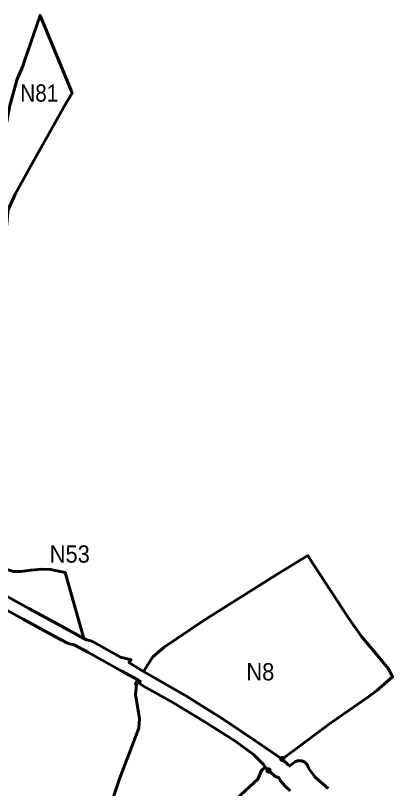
# Model space of a CAD drawing. Extents: x -650277 to -643422, y -1073980 to -1066720.
# Drawn here: x -645952 to -645426, y -1069207 to -1068130 of the extents above; entities that cross this region are included whole.
import ezdxf

# ---------------------------------------------------------------- set-up
doc = ezdxf.new("R2010")
doc.units = 0
doc.header["$LTSCALE"] = 9.6
doc.header["$PDMODE"] = 32
doc.header["$PDSIZE"] = 4.8
for name, color, linetype, lineweight in [('42', 7, 'Continuous', 60), ('48', 7, 'Continuous', 60), ('60', 7, 'Continuous', 60), ('63', 7, 'Continuous', 25), ('7', 7, 'Continuous', 60)]:
    doc.layers.add(name, color=color, linetype=linetype, lineweight=lineweight)

msp = doc.modelspace()

# ---------------------------------------------------------------- linework, layer by layer
at = {"layer": '42'}
for points in [[(-645973.36, -1068898.93), (-645954.59, -1068904.41), (-645944.23, -1068904.13), (-645930.1, -1068902.47), (-645915.61, -1068901.02), (-645902.91, -1068901.43), (-645882.63, -1068905.88), (-645856.26, -1068997.79)], [(-645856.26, -1068997.79), (-645892.77, -1068977.86), (-645933.28, -1068955.74), (-645975.31, -1068932.8), (-646017.55, -1068909.75)]]:
    msp.add_lwpolyline(points, dxfattribs=at)
at = {"layer": '48'}
msp.add_lwpolyline([(-645874.15, -1068234.44), (-645917.44, -1068129.99), (-645938.87, -1068193.06), (-645941.41, -1068200.54), (-645949.52, -1068218.72), (-645959.76, -1068255.23), (-645966.56, -1068292.38), (-645973.25, -1068342.08), (-645976.63, -1068393.14), (-645971.94, -1068405.38), (-645964.53, -1068429.83), (-645963.12, -1068415.21), (-645961.7, -1068400.54), (-645952.21, -1068378.95), (-645926.06, -1068332.18), (-645883.87, -1068256.88), (-645880.28, -1068250.47), (-645872.64, -1068238.08)], close=True, dxfattribs=at)
at = {"layer": '60'}
for points in [[(-645579.94, -1069165.52), (-645616.63, -1069140.8), (-645662.44, -1069109.89), (-645713.61, -1069078.06), (-645770.04, -1069045.34), (-645773.38, -1069043.46), (-645793.638, -1069031.021), (-645790.53, -1069027.19), (-645805.16, -1069023.52), (-645843.56, -1069002.41), (-645848.18, -1069000.48), (-645852.91, -1068999.62), (-645856.26, -1068997.79), (-645892.77, -1068977.86), (-645933.28, -1068955.74), (-645975.31, -1068932.8)], [(-645993.5, -1068942.1), (-645940.77, -1068970.74), (-645896.91, -1068994.75), (-645879.17, -1069004.02), (-645874.49, -1069005.73), (-645869.83, -1069006.45), (-645850.79, -1069016.84), (-645803.29, -1069042.92), (-645781.12, -1069055.29), (-645777.73, -1069057.2), (-645779.49, -1069059.92), (-645773.29, -1069063.99), (-645732.65, -1069086.82), (-645688.87, -1069113.44), (-645646.08, -1069140.37), (-645620.2, -1069159.26), (-645606.11, -1069172.98), (-645603.91, -1069176.86), (-645599, -1069181.48)], [(-645571.9, -1069173.43), (-645579.94, -1069165.52), (-645579.94, -1069165.52)], [(-645543.43, -1069178.39), (-645543.547, -1069177.727), (-645543.706, -1069177.053), (-645543.907, -1069176.37), (-645544.154, -1069175.682), (-645544.448, -1069174.993), (-645544.792, -1069174.308), (-645545.186, -1069173.63), (-645545.631, -1069172.966), (-645546.127, -1069172.32), (-645546.674, -1069171.699), (-645547.269, -1069171.107), (-645547.91, -1069170.551), (-645548.594, -1069170.034), (-645549.317, -1069169.563), (-645550.076, -1069169.141), (-645550.863, -1069168.772), (-645551.674, -1069168.459), (-645552.504, -1069168.203), (-645553.344, -1069168.007), (-645554.191, -1069167.87), (-645555.036, -1069167.793), (-645555.875, -1069167.772), (-645556.702, -1069167.808), (-645557.511, -1069167.896), (-645558.298, -1069168.035), (-645559.06, -1069168.219), (-645559.793, -1069168.445), (-645560.494, -1069168.709), (-645561.162, -1069169.007), (-645561.794, -1069169.334), (-645562.39, -1069169.686), (-645562.95, -1069170.06), (-645567.5, -1069173.46), (-645569.81, -1069175.03), (-645571.9, -1069173.43)], [(-645515.89, -1069206.66), (-645534.25, -1069190.56), (-645543.43, -1069178.39)], [(-645599, -1069181.48), (-645599, -1069181.48), (-645592.24, -1069187.73), (-645590.41, -1069189.45), (-645584.73, -1069191.88), (-645582.63, -1069195.88), (-645575.58, -1069203.57), (-645568.9, -1069209.87)]]:
    msp.add_lwpolyline(points, dxfattribs=at)
for p in [(-645579.94, -1069165.52), (-645599, -1069181.48)]:
    msp.add_point(p, dxfattribs=at)
at = {"layer": '7'}
msp.add_lwpolyline([(-645770.04, -1069045.34), (-645713.61, -1069078.06), (-645694.447, -1069089.98), (-645662.44, -1069109.89), (-645616.63, -1069140.8), (-645579.94, -1069165.52), (-645514.08, -1069116.5), (-645459.5, -1069078.59), (-645448.49, -1069070.45), (-645426.3, -1069051.02), (-645431.85, -1069039.83), (-645449.72, -1069018.58), (-645469.5, -1068995.09), (-645487.38, -1068969.87), (-645536.63, -1068894.79), (-645544.33, -1068882.17), (-645586.28, -1068907.71), (-645690.34, -1068973.16), (-645744.65, -1069009.71), (-645760.07, -1069023.11), (-645773.38, -1069043.46)], close=True, dxfattribs=at)
msp.add_lwpolyline([(-645643.34, -1069220.59), (-645613.9, -1069193.45), (-645608.71, -1069181.51), (-645603.91, -1069176.86), (-645606.11, -1069172.98), (-645620.2, -1069159.26), (-645646.08, -1069140.37), (-645688.87, -1069113.44), (-645732.65, -1069086.82), (-645773.29, -1069063.99), (-645779.49, -1069059.92), (-645777.73, -1069057.2), (-645781.12, -1069055.29), (-645784.69, -1069060.74), (-645783.02, -1069061.84), (-645784.52, -1069075.66), (-645778.75, -1069108.98), (-645779.685, -1069122.296), (-645806.806, -1069193.112), (-645840.644, -1069294.052)], dxfattribs=at)

# ---------------------------------------------------------------- texts
at = {"layer": '63'}
for s, width, p in [('N81', 0.9, (-645945, -1068250)), ('N53', 0.95, (-645904, -1068892)), ('N8', 0.95, (-645630, -1069056))]:
    msp.add_text(s, height=24, dxfattribs=dict(at, width=width)).set_placement(p)

doc.saveas('drawing.dxf')
